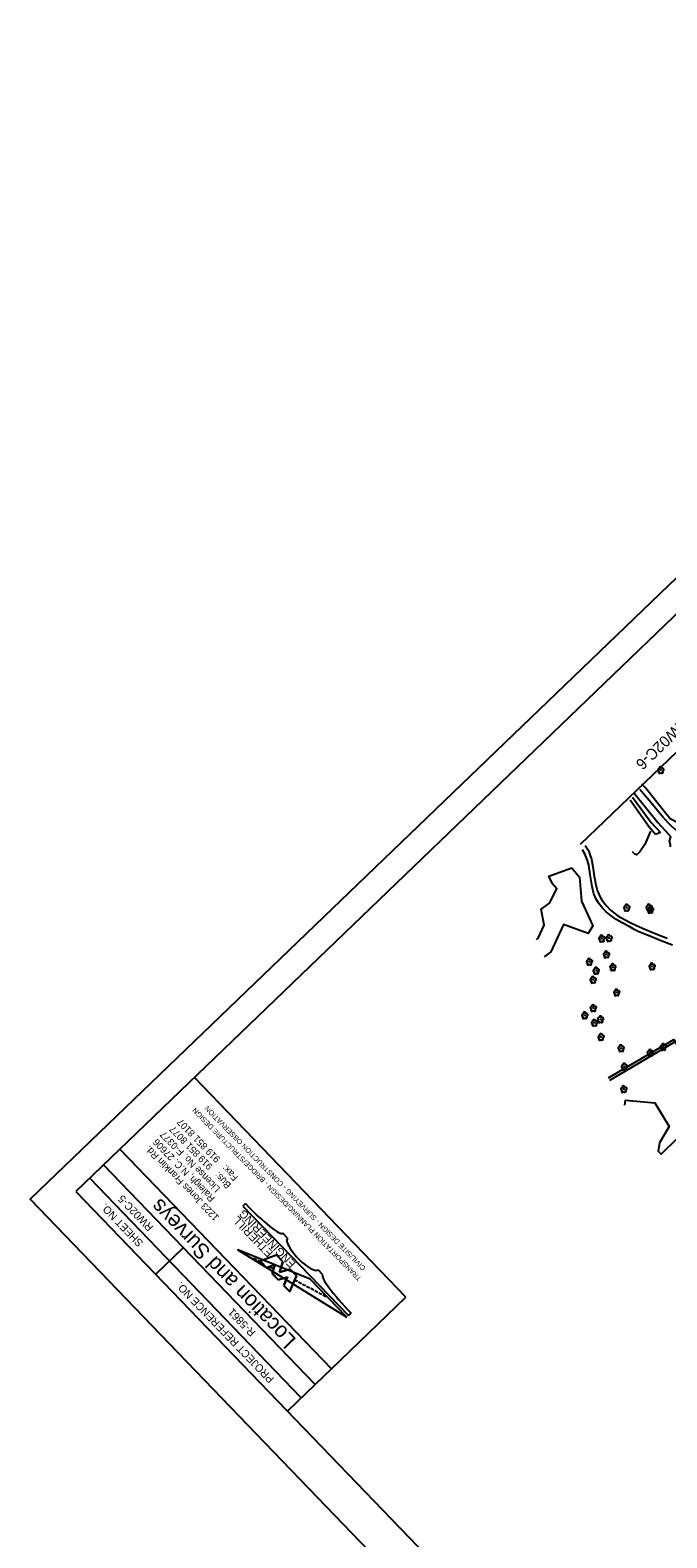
# Model space of a CAD drawing. Extents: x 474972 to 479313, y 498315 to 502691.
# Drawn here: x 474972 to 475891, y 500513 to 502691 of the extents above; entities that cross this region are included whole.
import ezdxf

# ---------------------------------------------------------------- set-up
doc = ezdxf.new("R2010")
doc.units = 0
for name, color, linetype in [('CTL Sheet Border CELL', 7, 'Continuous'), ('CTL Sheet Notes CELL', 7, 'Continuous'), ('Exist Other Culture Fence Line', 7, 'Continuous'), ('Exist Roads Soil', 7, 'Continuous'), ('Exist Vegetation Hedge Row', 7, 'Continuous'), ('Exist Vegetation Tree CELL', 7, 'Continuous'), ('Exist Vegetation Woods Line', 7, 'Continuous'), ('Matchline', 7, 'Continuous'), ('Matchline Text', 7, 'Continuous'), ('Sheet Plot Border Outside CELL', 7, 'Continuous')]:
    doc.layers.add(name, color=color, linetype=linetype)

msp = doc.modelspace()

# ---------------------------------------------------------------- linework, layer by layer
at = {"layer": 'CTL Sheet Border CELL'}
for p, q in [((475514.5, 500860.5), (475209, 501177.9)), ((475014.7, 501029.3), (475014.7, 501029.3)), ((475014.7, 501029.3), (475014.7, 501029.3)), ((475363.4, 500715.1), (475058, 501032.6)), ((474971.9, 501002.1), (474971.9, 501002.1)), ((475153.2, 500893.7), (475193.1, 500932.1)), ((475406.9, 500756.9), (475514.5, 500860.5)), ((475343.5, 500695.9), (475383.4, 500734.3))]:
    msp.add_line(p, q, dxfattribs=at)
for points in [[(475037.9, 501013.3), (477341.4, 498619.6), (479017, 500232), (476713.6, 502625.7)], [(475383.4, 500734.3), (475077.9, 501051.8), (475101.4, 501074.4), (475406.9, 500756.9)]]:
    msp.add_lwpolyline(points, close=True, dxfattribs=at)
at = {"layer": 'CTL Sheet Notes CELL'}
for p, q in [((475282.6, 500995.6), (475279, 500992.1)), ((475279, 500992.1), (475431.7, 500833.7)), ((475343.6, 500945.5), (475336.6, 500952.7)), ((475299, 500914.2), (475294.5, 500916.5)), ((475304.8, 500911), (475300.4, 500913.4)), ((475304, 500912.4), (475313.1, 500902.9)), ((475327.4, 500921), (475304.6, 500912.3)), ((475304.6, 500912.3), (475313.2, 500903.3)), ((475313.1, 500902.9), (475325.1, 500907.5)), ((475313.2, 500903.3), (475325.6, 500908)), ((475322.5, 500901.6), (475318.1, 500904)), ((475325.1, 500907.5), (475321, 500894.8)), ((475325.6, 500908), (475321.3, 500894.9)), ((475336.7, 500911.4), (475327.4, 500921)), ((475337, 500911.5), (475327.5, 500921.4)), ((475331.7, 500896.2), (475336.7, 500911.4)), ((475332.2, 500896.7), (475337, 500911.5)), ((475321, 500894.8), (475329.9, 500885.5)), ((475321.3, 500894.9), (475330, 500885.9)), ((475329.9, 500885.5), (475342.7, 500889.2)), ((475330, 500885.9), (475343.3, 500889.7)), ((475347.1, 500900.6), (475331.7, 500896.2)), ((475347.2, 500901), (475332.2, 500896.7)), ((475342.7, 500889.2), (475337.7, 500877.4)), ((475343.3, 500889.7), (475338.1, 500877.5)), ((475346.8, 500868.5), (475356.3, 500891)), ((475346.9, 500867.9), (475356.7, 500891.1)), ((475356.3, 500891), (475347.1, 500900.6)), ((475356.7, 500891.1), (475347.2, 500901)), ((475357.8, 500882.9), (475353.4, 500885.2)), ((475363.7, 500879.7), (475359.3, 500882.1)), ((475394.5, 500892.7), (475387.5, 500899.9)), ((475337.7, 500877.4), (475346.9, 500867.9)), ((475338.1, 500877.5), (475346.8, 500868.5)), ((475369.6, 500876.6), (475365.2, 500878.9)), ((475375.5, 500873.5), (475371.1, 500875.8)), ((475381.4, 500870.3), (475376.9, 500872.7)), ((475387.2, 500867.2), (475382.8, 500869.5)), ((475393.1, 500864.1), (475388.7, 500866.4)), ((475399, 500860.9), (475394.6, 500863.3)), ((475431.7, 500833.7), (475435.3, 500837.2))]:
    msp.add_line(p, q, dxfattribs=at)
msp.add_lwpolyline([(475429.3, 500831.4), (475376.1, 500886.6), (475271.7, 500928.7)], close=True, dxfattribs=at)
msp.add_lwpolyline([(475327.5, 500921.4), (475327.1, 500921.3), (475304, 500912.4)], dxfattribs=at)
for centre, major_axis, ratio, start_param, end_param in [((475289.2, 501001.9), (-47.4, 49.2), 0.134146, 1.570796, 3.141593), ((475365.5, 500922.7), (-22, 22.8), 0.289474, 0, 3.141593), ((475441.9, 500843.5), (47.4, -49.2), 0.134146, 3.141593, 4.712389)]:
    msp.add_ellipse(centre, major_axis=major_axis, ratio=ratio, start_param=start_param, end_param=end_param, dxfattribs=at)
at = {"layer": 'Exist Other Culture Fence Line'}
for points in [[(475867.5, 501534), (475859.4, 501514.4), (475852.1, 501503.7), (475848.5, 501500), (475847.3, 501499.6), (475845, 501500.3), (475841.7, 501503.9)], [(475806.9, 501177.3), (475813.9, 501181.5), (475901.3, 501232.6), (475913.9, 501211.1), (475974.4, 501253.2), (475996.9, 501268.3)]]:
    msp.add_lwpolyline(points, dxfattribs=at)
at = {"layer": 'Exist Roads Soil'}
for points in [[(475844.4, 501588.3), (475846.2, 501585.8), (475864.2, 501563.6), (475878.3, 501546.3)], [(475886.1, 501553.1), (475867.8, 501575.2), (475854.4, 501591.3), (475852.3, 501594.1)], [(475896.5, 501510.9), (475896.2, 501514.4), (475895.1, 501519.2), (475897, 501525.6), (475889.7, 501533.7), (475878.3, 501546.3)], [(475886.1, 501553.1), (475895.4, 501543.2), (475902.8, 501536.6), (475908.5, 501532.7), (475914.5, 501530.1), (475917.8, 501528.9), (475925.7, 501535.4), (475933.2, 501527.5), (475926.2, 501519.8), (475926.5, 501517.8), (475934.5, 501508.1), (475946.8, 501492.7), (475939.7, 501487), (475930.5, 501497), (475929.5, 501497.4), (475928.1, 501497.4), (475925, 501495), (475912.2, 501512.3), (475909, 501514.9), (475908.9, 501511.1)], [(475773, 501513.1), (475774.3, 501511.4), (475777.9, 501505.6), (475779.6, 501501.6), (475782.1, 501493.1), (475784.5, 501482.1), (475786.3, 501468.8), (475788.8, 501456), (475790.6, 501448.4), (475792.7, 501442.9), (475794.8, 501438.2), (475797.1, 501434.5), (475799.8, 501431.2), (475804.4, 501425.4), (475809.2, 501420), (475814, 501416.2), (475820.3, 501411.5), (475830.1, 501406), (475838.1, 501402), (475847.4, 501397.3), (475856, 501393.5), (475868.4, 501388.5), (475878.9, 501384), (475891.5, 501379.1)], [(475899.5, 501368.9), (475881.6, 501375.8), (475865.6, 501382.4), (475858, 501385.3), (475849.5, 501388.8), (475845, 501391.4), (475837.8, 501395.6), (475826.5, 501401.4), (475817.8, 501406), (475810.6, 501411.4), (475803.3, 501417.3), (475798.5, 501422.1), (475792.8, 501429.3), (475789.2, 501435.5), (475785.8, 501443.1), (475783.1, 501454), (475780.3, 501471.3), (475778.3, 501484.7), (475776.6, 501491.4), (475772.9, 501501.2), (475769.5, 501506.8)]]:
    msp.add_lwpolyline(points, dxfattribs=at)
at = {"layer": 'Exist Vegetation Hedge Row'}
for points in [[(475887.6, 501561.5), (475860.4, 501596.6), (475854.8, 501601.9)], [(475932.2, 501573.6), (475921.7, 501556), (475915.1, 501545.2), (475907.8, 501545.4), (475896.1, 501551.8), (475887.6, 501561.5)], [(475809, 501173.8), (475831, 501186.8), (475902.7, 501229.4), (475971.2, 501258), (476001.8, 501276.8), (476011.8, 501261.5), (476037, 501212.5), (476043.7, 501212.8), (476085.7, 501234.3), (476094.6, 501220.1), (476067, 501203.6), (476045.7, 501182.6)]]:
    msp.add_lwpolyline(points, dxfattribs=at)
at = {"layer": 'Exist Vegetation Tree CELL'}
for p, q in [((475882.4, 501622.1), (475882.4, 501622.1)), ((475833.2, 501423.2), (475833.2, 501423.2)), ((475865.6, 501423.5), (475865.6, 501423.5)), ((475867.4, 501420.3), (475867.4, 501420.3)), ((475797.2, 501378.7), (475797.2, 501378.7)), ((475807.8, 501379.4), (475807.8, 501379.4)), ((475779.3, 501345.1), (475779.3, 501345.1)), ((475803.9, 501355.8), (475803.9, 501355.8)), ((475784.7, 501319.1), (475784.7, 501319.1)), ((475789.1, 501332.3), (475789.1, 501332.3)), ((475813.3, 501337.2), (475813.3, 501337.2)), ((475869.9, 501338.4), (475869.9, 501338.4)), ((475818.7, 501300.8), (475818.7, 501300.8)), ((475784.9, 501278.1), (475784.9, 501278.1)), ((475772.5, 501267.6), (475772.5, 501267.6)), ((475786.6, 501257), (475786.6, 501257)), ((475795.4, 501261.9), (475795.4, 501261.9)), ((475796.1, 501236.3), (475796.1, 501236.3)), ((475825.1, 501220.2), (475825.1, 501220.2)), ((475867.2, 501213.5), (475867.2, 501213.5)), ((475886, 501222), (475886, 501222)), ((475829.8, 501193.5), (475829.8, 501193.5)), ((475828.9, 501161), (475828.9, 501161))]:
    msp.add_line(p, q, dxfattribs=at)
for centre in [(475882.4, 501622.1), (475833.2, 501423.2), (475865.6, 501423.5), (475867.4, 501420.3), (475797.2, 501378.7), (475807.8, 501379.4), (475779.3, 501345.1), (475803.9, 501355.8), (475869.9, 501338.4), (475784.7, 501319.1), (475789.1, 501332.3), (475813.3, 501337.2), (475818.7, 501300.8), (475784.9, 501278.1), (475772.5, 501267.6), (475786.6, 501257), (475795.4, 501261.9), (475796.1, 501236.3), (475825.1, 501220.2), (475867.2, 501213.5), (475886, 501222), (475829.8, 501193.5), (475828.9, 501161)]:
    msp.add_circle(centre, 0.326, dxfattribs=at)
for centre, radius, start, end in [((475879.8, 501622.2), 1.73, 62.6636, 279.3457), ((475882, 501624.9), 1.86, 330.1651, 219.7134), ((475884.9, 501622.7), 1.9, 257.1011, 134.1999), ((475880.7, 501618.9), 1.69, 111.5671, 6.231), ((475884.1, 501619.2), 1.7, 181.2822, 74.56), ((475832.8, 501426.1), 1.86, 330.1651, 219.7134), ((475865.2, 501426.4), 1.86, 330.1651, 219.7134), ((475868.1, 501424.1), 1.9, 257.1011, 134.1999), ((475830.6, 501423.3), 1.73, 62.6636, 279.3457), ((475831.5, 501420.1), 1.69, 111.5671, 6.231), ((475834.9, 501420.3), 1.7, 181.2822, 74.56), ((475835.8, 501423.8), 1.9, 257.1011, 134.1999), ((475863, 501423.7), 1.73, 62.6636, 279.3457), ((475863.9, 501420.4), 1.69, 111.5671, 6.231), ((475864.8, 501420.4), 1.73, 62.6636, 279.3457), ((475865.7, 501417.1), 1.69, 111.5671, 6.231), ((475867, 501423.1), 1.86, 330.1651, 219.7134), ((475867.2, 501420.6), 1.7, 181.2822, 74.56), ((475869.1, 501417.4), 1.7, 181.2822, 74.56), ((475869.9, 501420.9), 1.9, 257.1011, 134.1999), ((475796.8, 501381.5), 1.86, 330.1651, 219.7134), ((475807.4, 501382.2), 1.86, 330.1651, 219.7134), ((475794.6, 501378.8), 1.73, 62.6636, 279.3457), ((475795.5, 501375.5), 1.69, 111.5671, 6.231), ((475798.9, 501375.8), 1.7, 181.2822, 74.56), ((475799.7, 501379.3), 1.9, 257.1011, 134.1999), ((475803.5, 501358.6), 1.86, 330.1651, 219.7134), ((475805.2, 501379.5), 1.73, 62.6636, 279.3457), ((475806.1, 501376.2), 1.69, 111.5671, 6.231), ((475809.4, 501376.5), 1.7, 181.2822, 74.56), ((475810.3, 501380), 1.9, 257.1011, 134.1999), ((475776.7, 501345.3), 1.73, 62.6636, 279.3457), ((475777.6, 501342), 1.69, 111.5671, 6.231), ((475778.9, 501348), 1.86, 330.1651, 219.7134), ((475780.9, 501342.2), 1.7, 181.2822, 74.56), ((475781.8, 501345.7), 1.9, 257.1011, 134.1999), ((475801.3, 501355.9), 1.73, 62.6636, 279.3457), ((475802.2, 501352.6), 1.69, 111.5671, 6.231), ((475805.6, 501352.9), 1.7, 181.2822, 74.56), ((475806.5, 501356.3), 1.9, 257.1011, 134.1999), ((475810.7, 501337.4), 1.73, 62.6636, 279.3457), ((475812.9, 501340.1), 1.86, 330.1651, 219.7134), ((475815.8, 501337.8), 1.9, 257.1011, 134.1999), ((475867.3, 501338.5), 1.73, 62.6636, 279.3457), ((475869.5, 501341.2), 1.86, 330.1651, 219.7134), ((475872.4, 501339), 1.9, 257.1011, 134.1999), ((475782.1, 501319.3), 1.73, 62.6636, 279.3457), ((475783, 501316), 1.69, 111.5671, 6.231), ((475784.3, 501322), 1.86, 330.1651, 219.7134), ((475786.5, 501332.4), 1.73, 62.6636, 279.3457), ((475786.4, 501316.2), 1.7, 181.2822, 74.56), ((475787.4, 501329.1), 1.69, 111.5671, 6.231), ((475787.2, 501319.7), 1.9, 257.1011, 134.1999), ((475788.7, 501335.1), 1.86, 330.1651, 219.7134), ((475790.7, 501329.4), 1.7, 181.2822, 74.56), ((475791.6, 501332.9), 1.9, 257.1011, 134.1999), ((475811.6, 501334.1), 1.69, 111.5671, 6.231), ((475815, 501334.3), 1.7, 181.2822, 74.56), ((475868.2, 501335.3), 1.69, 111.5671, 6.231), ((475871.6, 501335.5), 1.7, 181.2822, 74.56), ((475816.1, 501301), 1.73, 62.6636, 279.3457), ((475817, 501297.7), 1.69, 111.5671, 6.231), ((475818.3, 501303.7), 1.86, 330.1651, 219.7134), ((475820.3, 501297.9), 1.7, 181.2822, 74.56), ((475821.2, 501301.4), 1.9, 257.1011, 134.1999), ((475782.3, 501278.3), 1.73, 62.6636, 279.3457), ((475783.2, 501275), 1.69, 111.5671, 6.231), ((475784.5, 501281), 1.86, 330.1651, 219.7134), ((475786.6, 501275.2), 1.7, 181.2822, 74.56), ((475787.5, 501278.7), 1.9, 257.1011, 134.1999), ((475769.9, 501267.8), 1.73, 62.6636, 279.3457), ((475770.8, 501264.5), 1.69, 111.5671, 6.231), ((475772.1, 501270.5), 1.86, 330.1651, 219.7134), ((475774.2, 501264.7), 1.7, 181.2822, 74.56), ((475775.1, 501268.2), 1.9, 257.1011, 134.1999), ((475784, 501257.2), 1.73, 62.6636, 279.3457), ((475784.9, 501253.9), 1.69, 111.5671, 6.231), ((475786.2, 501259.9), 1.86, 330.1651, 219.7134), ((475788.3, 501254.1), 1.7, 181.2822, 74.56), ((475789.1, 501257.6), 1.9, 257.1011, 134.1999), ((475792.8, 501262.1), 1.73, 62.6636, 279.3457), ((475793.7, 501258.8), 1.69, 111.5671, 6.231), ((475795, 501264.8), 1.86, 330.1651, 219.7134), ((475797, 501259), 1.7, 181.2822, 74.56), ((475797.9, 501262.5), 1.9, 257.1011, 134.1999), ((475793.5, 501236.5), 1.73, 62.6636, 279.3457), ((475794.4, 501233.2), 1.69, 111.5671, 6.231), ((475795.7, 501239.2), 1.86, 330.1651, 219.7134), ((475797.7, 501233.4), 1.7, 181.2822, 74.56), ((475798.6, 501236.9), 1.9, 257.1011, 134.1999), ((475822.5, 501220.3), 1.73, 62.6636, 279.3457), ((475823.4, 501217.1), 1.69, 111.5671, 6.231), ((475824.7, 501223.1), 1.86, 330.1651, 219.7134), ((475826.8, 501217.3), 1.7, 181.2822, 74.56), ((475827.6, 501220.8), 1.9, 257.1011, 134.1999), ((475864.6, 501213.7), 1.73, 62.6636, 279.3457), ((475865.5, 501210.4), 1.69, 111.5671, 6.231), ((475866.8, 501216.4), 1.86, 330.1651, 219.7134), ((475868.9, 501210.6), 1.7, 181.2822, 74.56), ((475869.8, 501214.1), 1.9, 257.1011, 134.1999), ((475883.4, 501222.1), 1.73, 62.6636, 279.3457), ((475884.3, 501218.8), 1.69, 111.5671, 6.231), ((475885.6, 501224.8), 1.86, 330.1651, 219.7134), ((475887.7, 501219.1), 1.7, 181.2822, 74.56), ((475888.5, 501222.5), 1.9, 257.1011, 134.1999), ((475827.2, 501193.7), 1.73, 62.6636, 279.3457), ((475828.1, 501190.4), 1.69, 111.5671, 6.231), ((475829.4, 501196.4), 1.86, 330.1651, 219.7134), ((475831.4, 501190.6), 1.7, 181.2822, 74.56), ((475832.3, 501194.1), 1.9, 257.1011, 134.1999), ((475828.5, 501163.8), 1.86, 330.1651, 219.7134), ((475826.3, 501161.1), 1.73, 62.6636, 279.3457), ((475827.2, 501157.9), 1.69, 111.5671, 6.231), ((475830.6, 501158.1), 1.7, 181.2822, 74.56), ((475831.4, 501161.6), 1.9, 257.1011, 134.1999)]:
    msp.add_arc(centre, radius, start, end, dxfattribs=at)
at = {"layer": 'Exist Vegetation Woods Line'}
for p, q in [((475865.7, 501539.7), (475838.4, 501578.4)), ((475841.6, 501583.1), (475868.7, 501546.4))]:
    msp.add_line(p, q, dxfattribs=at)
for points in [[(475874.8, 501528.8), (475865.7, 501539.7)], [(475868.7, 501546.4), (475881.8, 501532)], [(475881.8, 501532), (475874.8, 501528.8)], [(475754.1, 501480.6), (475764.9, 501467.3), (475767.7, 501432.8), (475784.5, 501397.2), (475777.3, 501385.7), (475741.9, 501398.8), (475723.7, 501359.3), (475713.9, 501352.2)], [(475726.2, 501457.9), (475720.9, 501468.7), (475754.1, 501480.6)], [(475702.7, 501377), (475705.1, 501379.3), (475714.2, 501397.9), (475709.7, 501420.9), (475721.9, 501429.9), (475732.2, 501450.5), (475726.2, 501457.9)], [(475830.3, 501138), (475831.3, 501145), (475873.7, 501141.1), (475894.6, 501107.1), (475880.6, 501083.4), (475878.7, 501071.6), (475882.9, 501067.2), (475907.1, 501090.5), (475926.2, 501084.4), (475961.9, 501060.1), (475949.3, 501020.5), (475939.2, 500985.9), (475928.2, 500977.8)]]:
    msp.add_lwpolyline(points, dxfattribs=at)
at = {"layer": 'Matchline'}
msp.add_line((475766.5, 501515), (476126.8, 501861.7), dxfattribs=at)
at = {"layer": 'Sheet Plot Border Outside CELL'}
msp.add_lwpolyline([(479313.3, 500003.9), (476727.3, 502691.2), (474971.9, 501002.1), (477557.9, 498314.7)], close=True, dxfattribs=at)

# ---------------------------------------------------------------- texts
at = {"layer": 'CTL Sheet Border CELL'}
for s, height, p in [('SHEET NO.', 11.07, (475136, 500939.6)), ('RW02C-5', 11.07, (475150.6, 500962.2)), ('Location and Surveys', 22.147, (475357.2, 500799.3)), ('PROJECT REFERENCE NO.', 11.074, (475324.9, 500742.9)), ('R-5861', 11.07, (475298.2, 500810.2))]:
    msp.add_text(s, height=height, rotation=133.8985, dxfattribs=at).set_placement(p)
at = {"layer": 'CTL Sheet Notes CELL'}
for s, height, rotation, p in [('TRANSPORTATION PLANNING/DESIGN - BRIDGE/STRUCTURE DESIGN', 7.333, 134.2745, (475450.9, 500888.2)), ('CIVIL/SITE DESIGN - SURVEYING - CONSTRUCTION OBSERVATION', 7.333, 134.2745, (475457, 500903)), ('Bus:   919 851 8077', 10, 134.2745, (475262.7, 501023.1)), ('Fax:   919 851 8107', 10, 134.2745, (475273, 501034.1)), ('1223 Jones Franklin Rd. ', 10, 134.2745, (475245.3, 500976.5)), ('Raleigh, N.C. 27606', 10, 134.2745, (475239.4, 501004)), ('License No. F-0377', 10, 134.2745, (475247, 501017.7)), ('ETHERILL', 11.67, 133.9481, (475323.5, 500925)), ('ENGINEERING', 11.667, 133.9481, (475356.3, 500909.5))]:
    msp.add_text(s, height=height, rotation=rotation, dxfattribs=at).set_placement(p)
at = {"layer": 'Matchline Text'}
msp.add_text('MATCHLINE SHEET RW02C-6', height=16, rotation=224.2987, dxfattribs=at).set_placement((476060.2, 501842.7))

doc.saveas('drawing.dxf')
